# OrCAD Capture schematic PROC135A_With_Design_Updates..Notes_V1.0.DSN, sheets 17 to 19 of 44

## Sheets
17 17. M.2 CONNECTOR: size C; title: M.2 CONNECTOR I/F
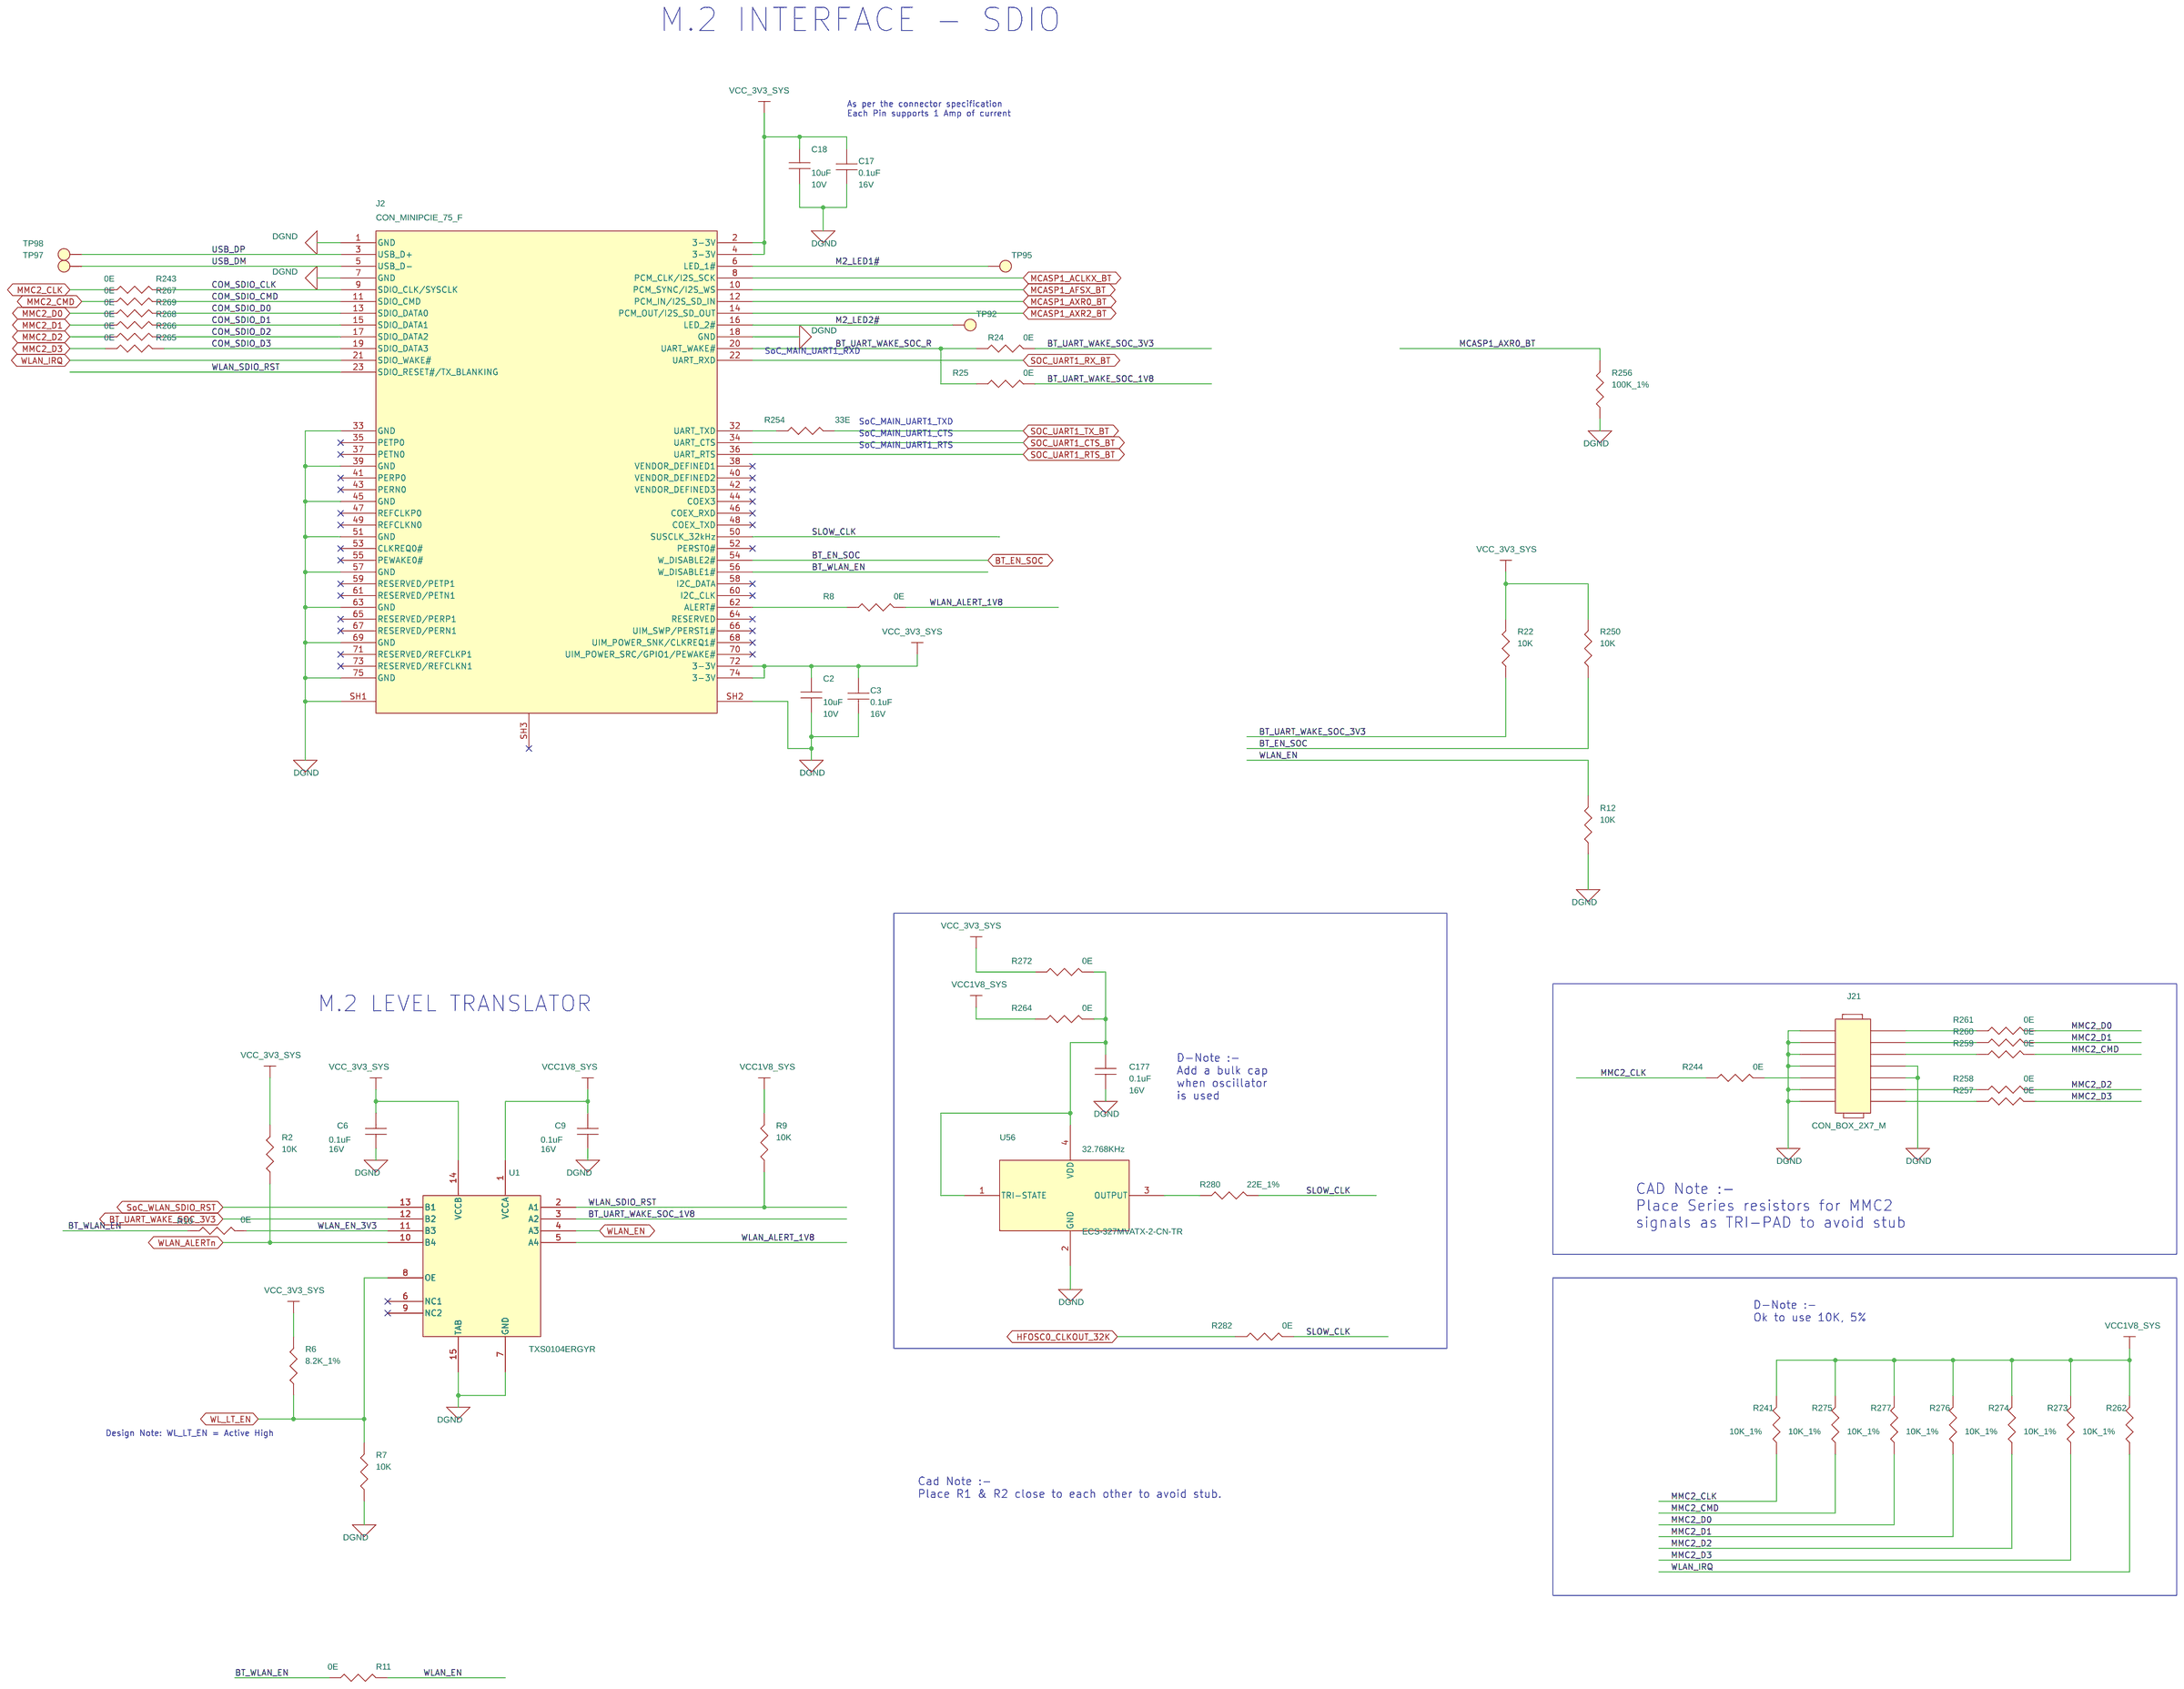
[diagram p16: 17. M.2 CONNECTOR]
18 18. eMMC FLASH: size C; title: eMMC FLASH INTERFACE
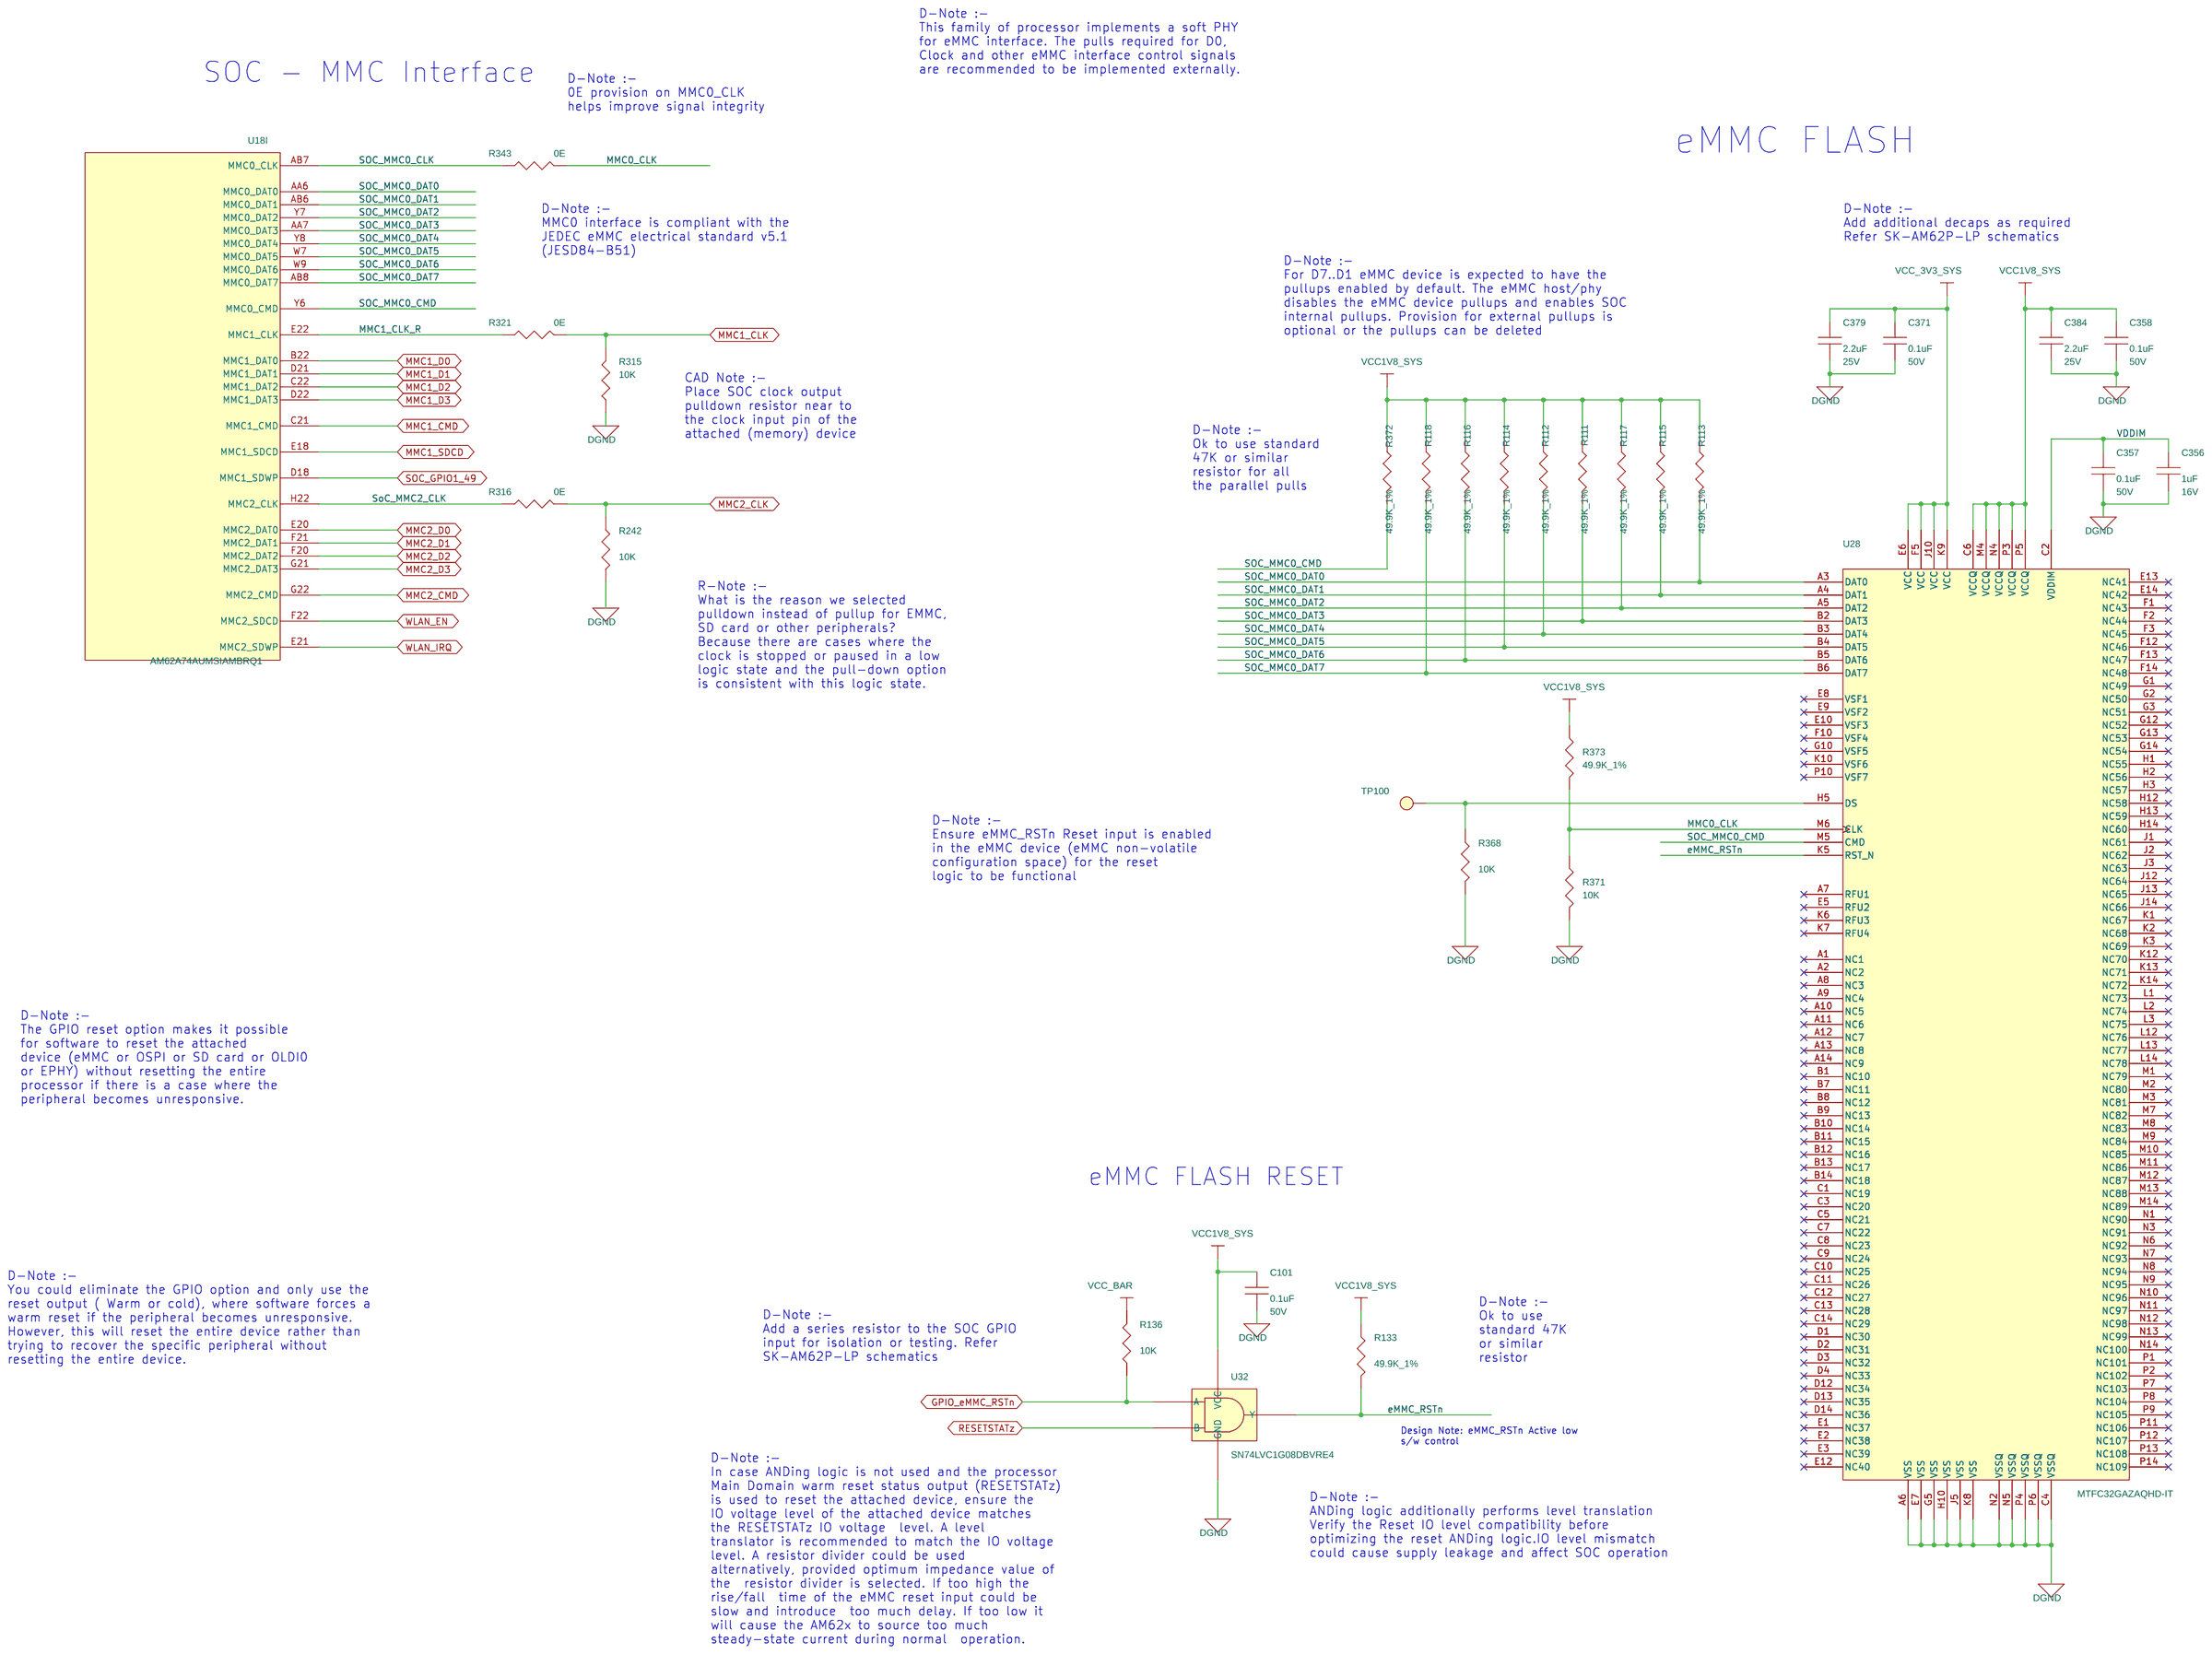
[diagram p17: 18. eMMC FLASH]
19 19. SD CARD INTERFACE: size C; title: SD CARD INTERFACE
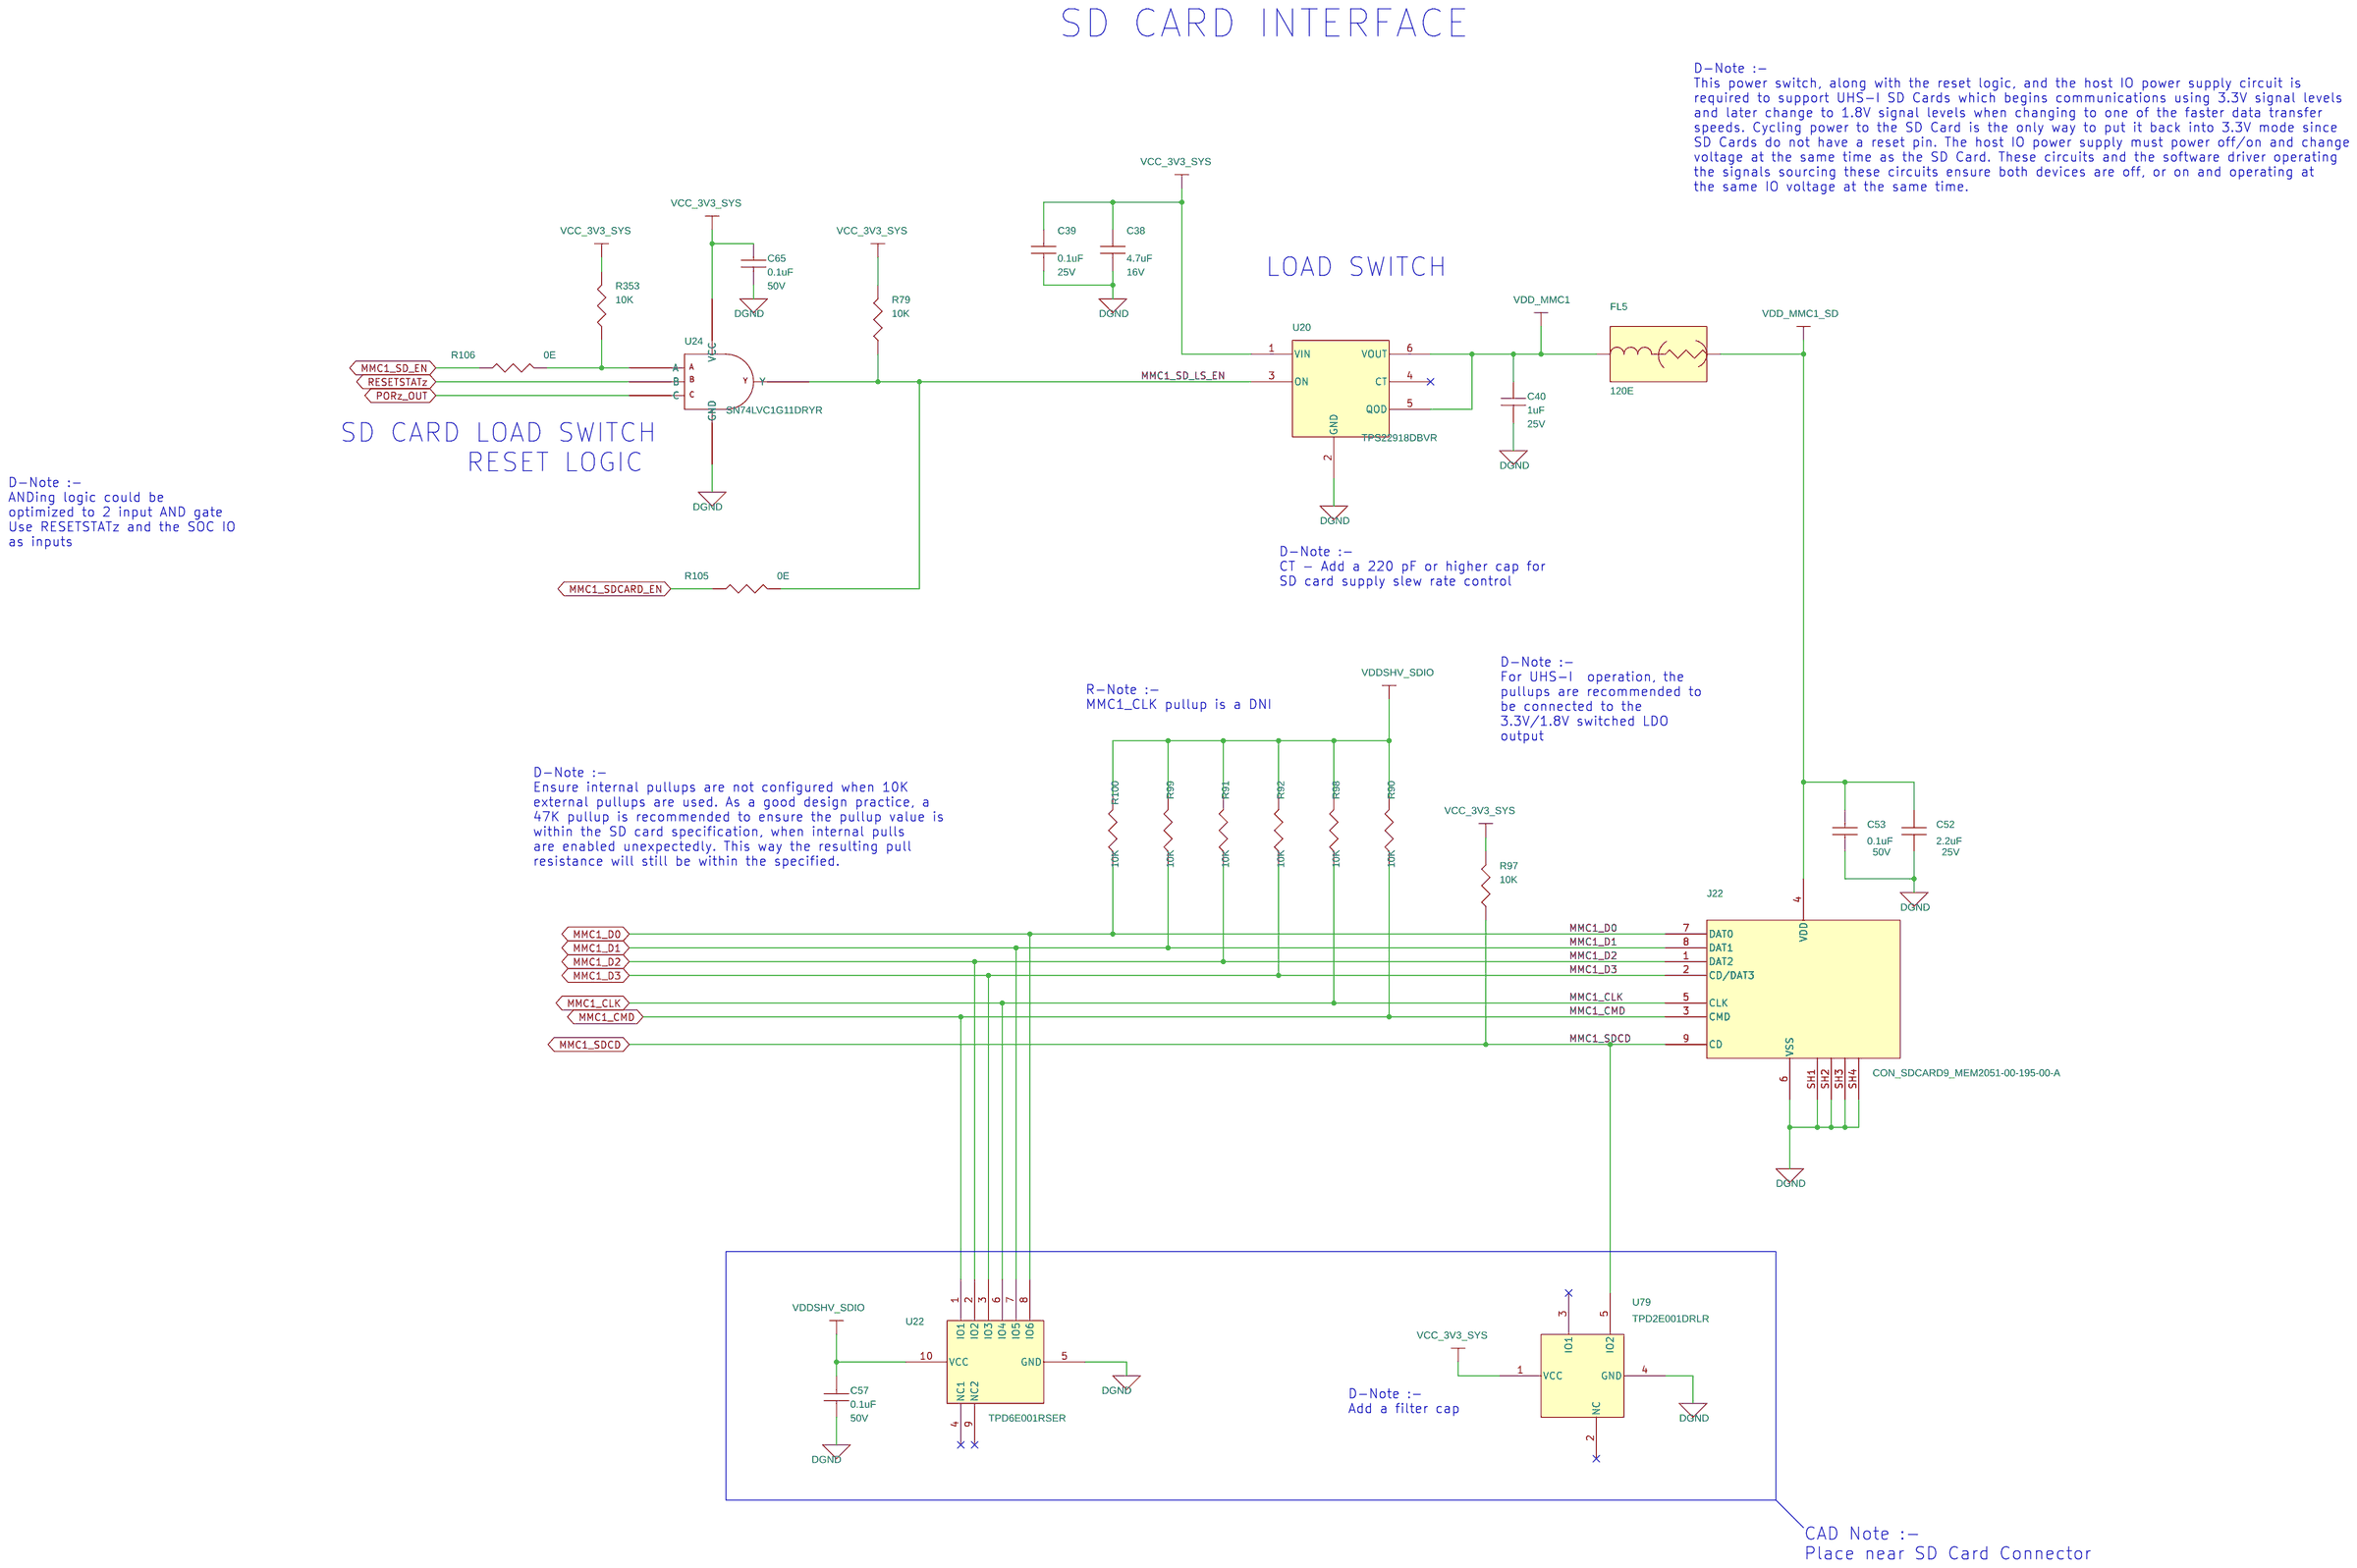
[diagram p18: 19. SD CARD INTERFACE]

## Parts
sheet 17. M.2 CONNECTOR
C2  10uF  [CAP0402_0-75]
C3  0.1uF  [CAP0201_0-5]
C6  0.1uF  [CAP0201_0-5]
C9  0.1uF  [CAP0201_0-5]
C17  0.1uF  [CAP0201_0-5]
C18  10uF  [CAP0402_0-75]
C177  0.1uF  [CAP0201_0-5]
J2  CON_MINIPCIE_75_F  [CON_MINIPCI75_2199119-4_S_R_S_3-2_2230]
J21  CON_BOX_2X7_M  [CON_BOX2X7_3020-14-0300-00_P_S_S_10-4]
R2  10K  [RES0201_0-5]
R6  8.2K_1%  [RES0201_0-5]
R7  10K  [RES0201_0-5]
R8  0E  [RES0201_0-5]
R9  10K  [RES0201_0-5]
R10  0E  [RES0201_0-5]
R11  0E  [RES0201_0-5]
R12  10K  [RES0201_0-5]
R22  10K  [RES0201_0-5]
R24  0E  [RES0201_0-5]
R25  0E  [RES0201_0-5]
R241  10K_1%  [RES0201_0-5]
R243  0E  [RES0201_0-5]
R244  0E  [RES0201_0-5]
R250  10K  [RES0201_0-5]
R254  33E  [RES0201_0-5]
R256  100K_1%  [RES0402_0-5]
R257  0E  [RES0201_0-5]
R258  0E  [RES0201_0-5]
R259  0E  [RES0201_0-5]
R260  0E  [RES0201_0-5]
R261  0E  [RES0201_0-5]
R262  10K_1%  [RES0201_0-5]
R264  0E  [RES0201_0-5]
R265  0E  [RES0201_0-5]
R266  0E  [RES0201_0-5]
R267  0E  [RES0201_0-5]
R268  0E  [RES0201_0-5]
R269  0E  [RES0201_0-5]
R272  0E  [RES0201_0-5]
R273  10K_1%  [RES0201_0-5]
R274  10K_1%  [RES0201_0-5]
R275  10K_1%  [RES0201_0-5]
R276  10K_1%  [RES0201_0-5]
R277  10K_1%  [RES0201_0-5]
R280  22E_1%  [RES0201_0-5]
R282  0E  [RES0201_0-5]
TP92  TP20_SMD  [TP20_SMD]
TP95  TP20_SMD  [TP20_SMD]
TP97  TP20_SMD  [TP20_SMD]
TP98  TP20_SMD  [TP20_SMD]
U1  TXS0104ERGYR  [QFN14_19-68_145X145]
U56  32.768KHz  [OSC4_ECS-327MVATX-2_100X80_SMD_1]
sheet 18. eMMC FLASH
C101  0.1uF  [CAP0402_0-75]
C356  1uF  [CAP0201_0-5]
C357  0.1uF  [CAP0402_0-75]
C358  0.1uF  [CAP0402_0-75]
C371  0.1uF  [CAP0402_0-75]
C379  2.2uF  [CAP0402_0-75]
C384  2.2uF  [CAP0402_0-75]
R111  49.9K_1%  [RES0201_0-5]
R112  49.9K_1%  [RES0201_0-5]
R113  49.9K_1%  [RES0201_0-5]
R114  49.9K_1%  [RES0201_0-5]
R115  49.9K_1%  [RES0201_0-5]
R116  49.9K_1%  [RES0201_0-5]
R117  49.9K_1%  [RES0201_0-5]
R118  49.9K_1%  [RES0201_0-5]
R133  49.9K_1%  [RES0201_0-5]
R136  10K  [RES0201_0-5]
R242  10K  [RES0201_0-5]
R315  10K  [RES0201_0-5]
R316  0E  [RES0201_0-5]
R321  0E  [RES0201_0-5]
R343  0E  [RES0201_0-5]
R368  10K  [RES0201_0-5]
R371  10K  [RES0201_0-5]
R372  49.9K_1%  [RES0201_0-5]
R373  49.9K_1%  [RES0201_0-5]
TP100  TP20_SMD  [TP20_SMD]
U28  MTFC32GAZAQHD-IT  [VFBGA153_19-68_460X520_0-9]
U32  SN74LVC1G08DBVRE4  [SOT23-5]
sheet 19. SD CARD INTERFACE
C38  4.7uF  [CAP0402_0-75]
C39  0.1uF  [CAP0201_0-5]
C40  1uF  [CAP0402_0-75]
C52  2.2uF  [CAP0402_0-75]
C53  0.1uF  [CAP0402_0-75]
C57  0.1uF  [CAP0402_0-75]
C65  0.1uF  [CAP0402_0-75]
FL5  120E  [EMIFIL_BLM15A_0402_0-6]
J22  CON_SDCARD9_MEM2051-00-195-00-A  [CON_SD9_MEM2051-00-195-00_S_R_S_2-1]
R79  10K  [RES0201_0-5]
R90  10K  [RES0201_0-5]
R91  10K  [RES0201_0-5]
R92  10K  [RES0201_0-5]
R97  10K  [RES0201_0-5]
R98  10K  [RES0201_0-5]
R99  10K  [RES0201_0-5]
R100  10K  [RES0201_0-5]
R105  0E  [RES0201_0-5]
R106  0E  [RES0201_0-5]
R353  10K  [RES0201_0-5]
U20  TPS22918DBVR  [SOT23-6]
U22  TPD6E001RSER  [UQFN10_19-68_80X60_0-6]
U24  SN74LVC1G11DRYR  [SON6_SN74LVC2G17_40X60_0-6]
U79  TPD2E001DRLR  [SOT553-5_0-6]
sheet 41. OSCILLATOR
U18  AM62A74AUMSIAMBRQ1  [FBGA484_31-49_710X710_2-7]  (sections A,B,C,D,E,F,G,H,I,J,K,L,M,N,O,P,Q)

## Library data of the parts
C2 C18 = CAP: CAP CERAMIC 10uF 10V 20% X5R 0402; Chkd/date: MANIRAJA/300520; Crtd /date: ALVY/260520; Custom_Duty: 15%; Customs_HS_Code: 85322990; Distributor_name: DIGIKEY; Distributor_part_number: 490-GRM155R61A106ME11DTR-ND; Footprint Path: Y:\MIS_DATABASE\Library\ALTIUM_TOOL\PCB_FOOTPRINTS\Altium_Footprint_Lib.PcbLib; Height: 0.55MM; Library Path: Y:\MIS_DATABASE\Library\ALTIUM_TOOL\SCHEMATICS_PARTS\MS_DISCRETE_Library.schlib; Mfr_name: MURATA; Mfr_part_number: GRM155R61A106ME11D; Mistral Part No: 120013110019-R; Package: 0402; Part_type: CAPACITORS\CERAMIC; Project: QCS610_NANOSOM; RoHS: RoHS; Temperature: -55°C+85°C; Tolerance: 20%; Voltage: 10V; Wattage: NA; Weight: 3.1mg; Datasheet: Y:\MIS_DATABASE\DATASHEETS\CAPACITORS\MURATA-GXX-SER_NOV17.PDF
C3 C6 C9 C17 C177 = CAP: CAP CERAMIC 0.1uF 16V 10% X5R 0201; Alt_Mfr_name: YAGEO AMERICA; Alt_Mfr_part_number: CC0402KRX5R8BB104; Chkd/date: MANIRAJA/230118; Crtd /date: MANIRAJA/230118; Custom_Duty: 15%; Customs_HS_Code: 85322990; Distributor_name: DIGIKEY; Distributor_part_number: 490-14305-1-ND; Footprint Path: Y:\MIS_DATABASE\Library\ALTIUM_TOOL\PCB_FOOTPRINTS\Altium_Footprint_Lib.PcbLib; Height: 0.33MM; Library Path: Y:\MIS_DATABASE\Library\ALTIUM_TOOL\SCHEMATICS_PARTS\MS_DISCRETE_Library.schlib; Mfr_name: MURATA; Mfr_part_number: GRM033R61C104KE14D; Mistral Part No: 120009030072-R; Package: 0201; Part_type: CAPACITORS\CERAMIC; Project: TI_MAXIE_CPB; RoHS: RoHS; Temperature: -55°C+85°C; Tolerance: 10%; Voltage: 16V; Wattage: NA; Weight: 0.33mg; Datasheet: Y:\MIS_DATABASE\DATASHEETS\CAPACITORS\GRM033R61C104KE14.PDF
J2 = CON_PCI_75_2199119-4_2230: CON MINIPCI 75POS 0.50MM PITCH FEMALE RT SMD; Chkd/date: ALVY/300521; Crtd /date: ALVY/300521; Custom_Duty: 24%; Customs_HS_Code: 85369090; Distributor_name: DIGIKEY; Distributor_part_number: A115900CT-ND; Footprint Path: Y:\MIS_DATABASE\Library\ALTIUM_TOOL\PCB_FOOTPRINTS\Altium_Footprint_Lib.PcbLib; Height: 3.20MM; Library Path: Y:\MIS_DATABASE\Library\ALTIUM_TOOL\SCHEMATICS_PARTS\MS_CONNECTOR_Library.schlib; Mfr_name: TE CONNECTIVITY; Mfr_part_number: 2199119-4_2230; Mistral Part No: 150021030016-R; Package: SMD; Part_type: CONNECTOR\PCI; Project: VOLTA_CHARGER V5; RoHS: RoHS; Temperature: -40°C+80°C; Tolerance: NA; Voltage: NA; Wattage: NA; Weight: 506mg; Datasheet: Y:\MIS_DATABASE\DATASHEETS\CONNECTORS\2199119.PDF
J21 = HEADER_7X2: CON BOX 2X7 2.54MM PITCH MALE ST SMD; Chkd/date: MANIRAJA/080921; Crtd /date: ALVY/080921; Custom_Duty: 24%; Customs_HS_Code: 85369090; Distributor_name: DIGIKEY; Distributor_part_number: 1175-1622-ND; Footprint Path: Y:\MIS_DATABASE\Library\ALTIUM_TOOL\PCB_FOOTPRINTS\Altium_Footprint_Lib.PcbLib; Height: 10.32MM; Library Path: Y:\MIS_DATABASE\Library\ALTIUM_TOOL\SCHEMATICS_PARTS\MS_CONNECTOR_Library.schlib; Mfr_name: CnC TECH; Mfr_part_number: 3020-14-0300-00; Mistral Part No: 150021090012-R; Package: SMD; Part_type: CONNECTOR\BOX HEADERS; Project: TI_AM335x SK_BRD; RoHS: RoHS; Temperature: -40°C+105°C; Tolerance: NA; Voltage: NA; Wattage: NA; Weight: NA; Datasheet: Y:\MIS_DATABASE\DATASHEETS\CONNECTORS\3020-XX-0300-00.PDF
R2 R7 R9 R12 R22 R79 R90-R92 R97-R100 R136 R242 R250 R315 R353 R368 R371 = RESISTOR: RES 10K 1/20W 5% 0201; Chkd/date: MANIRAJA/050517; Crtd /date: MANIRAJA/050517; Custom_Duty: 15%; Customs_HS_Code: 85332119; Distributor_name: DIGIKEY; Distributor_part_number: 311-10KNCT-ND; Footprint Path: Y:\MIS_DATABASE\Library\ALTIUM_TOOL\PCB_FOOTPRINTS\Altium_Footprint_Lib.PcbLib; Height: 0.26MM; Library Path: Y:\MIS_DATABASE\Library\ALTIUM_TOOL\SCHEMATICS_PARTS\MS_DISCRETE_Library.schlib; Mfr_name: YAGEO AMERICA; Mfr_part_number: RC0201JR-0710KL; Mistral Part No: 110010070051-R; Package: 0201; Part_type: RESISTORS\FIXED; Project: GOLDEN-I LITE; RoHS: RoHS; Temperature: -55°C+125°C; Tolerance: 5%; Voltage: NA; Wattage: 1/20W; Weight: 0.17mg; Datasheet: Y:\MIS_DATABASE\DATASHEETS\RESISTORS\RCXXXXL-SER_MAR18.PDF
R6 = RESISTOR: RES 8.2K 1/20W 1% 0201; Chkd/date: SUHAS/230910; Crtd /date: MUDDU/060710; Custom_Duty: 15%; Customs_HS_Code: 85332119; Distributor_name: DIGIKEY; Distributor_part_number: 541-8.20KAABCT-ND; Footprint Path: Y:\MIS_DATABASE\Library\ALTIUM_TOOL\PCB_FOOTPRINTS\Altium_Footprint_Lib.PcbLib; Height: 0.28MM; Library Path: Y:\MIS_DATABASE\Library\ALTIUM_TOOL\SCHEMATICS_PARTS\MS_DISCRETE_Library.schlib; Mfr_name: VISHAY; Mfr_part_number: CRCW02018K20FKED; Mistral Part No: 110010070001-R; Package: 0201; Part_type: RESISTORS\FIXED; Project: PB_BUGBASE; RoHS: RoHS; Temperature: -55°C+155°C; Tolerance: 1%; Voltage: NA; Wattage: 1/20W; Weight: 0.17mg; Datasheet: Y:\MIS_DATABASE\DATASHEETS\RESISTORS\CRCW0201.PDF
R8 R10 R11 R24 R25 R105 R106 R243 R244 R257-R261 R264-R269 R272 R282 = RESISTOR: RES 0E 1/20W 5% 0201; Chkd/date: NAVEED/301214; Crtd /date: MUDDU/120710; Custom_Duty: 15%; Customs_HS_Code: 85332119; Distributor_name: DIGIKEY; Distributor_part_number: 311-0.0NCT-ND; Footprint Path: Y:\MIS_DATABASE\Library\ALTIUM_TOOL\PCB_FOOTPRINTS\Altium_Footprint_Lib.PcbLib; Height: 0.26MM; Library Path: Y:\MIS_DATABASE\Library\ALTIUM_TOOL\SCHEMATICS_PARTS\MS_DISCRETE_Library.schlib; Mfr_name: YAGEO AMERICA; Mfr_part_number: RC0201JR-070RL; Mistral Part No: 110010070067-R; Package: 0201; Part_type: RESISTORS\FIXED; Project: PB_BUGBASE; RoHS: RoHS; Temperature: -55°C+125°C; Tolerance: 5%; Voltage: NA; Wattage: 1/20W; Weight: 0.17mg; Datasheet: Y:\MIS_DATABASE\DATASHEETS\RESISTORS\RCXXXXL-SER_MAR18.PDF
R241 R262 R273-R277 = RESISTOR: RES 10K 1/20W 1% 0201; Chkd/date: VASANTHA/270117; Crtd /date: MANIRAJA/270117; Custom_Duty: 15%; Customs_HS_Code: 85332119; Distributor_name: DIGIKEY; Distributor_part_number: 311-10.0KMCT-ND; Footprint Path: Y:\MIS_DATABASE\Library\ALTIUM_TOOL\PCB_FOOTPRINTS\Altium_Footprint_Lib.PcbLib; Height: 0.26MM; Library Path: Y:\MIS_DATABASE\Library\ALTIUM_TOOL\SCHEMATICS_PARTS\MS_DISCRETE_Library.schlib; Mfr_name: YAGEO AMERICA; Mfr_part_number: RC0201FR-0710KL; Mistral Part No: 110011040018-R; Package: 0201; Part_type: RESISTORS\FIXED; Project: GOLDEN-I LITE; RoHS: RoHS; Temperature: -55°C+125°C; Tolerance: 1%; Voltage: NA; Wattage: 1/20W; Weight: 0.17mg; Datasheet: Y:\MIS_DATABASE\DATASHEETS\RESISTORS\RCXXXXL-SER_MAR18.PDF
R254 = RESISTOR: RES 33E 1/20W 5% 0201; Chkd/date: MANIRAJA/050517; Crtd /date: MANIRAJA/050517; Custom_Duty: 15%; Customs_HS_Code: 85332119; Distributor_name: DIGIKEY; Distributor_part_number: 311-33NCT-ND; Footprint Path: Y:\MIS_DATABASE\Library\ALTIUM_TOOL\PCB_FOOTPRINTS\Altium_Footprint_Lib.PcbLib; Height: 0.26MM; Library Path: Y:\MIS_DATABASE\Library\ALTIUM_TOOL\SCHEMATICS_PARTS\MS_DISCRETE_Library.schlib; Mfr_name: YAGEO AMERICA; Mfr_part_number: RC0201JR-0733RL; Mistral Part No: 110010070052-R; Package: 0201; Part_type: RESISTORS\FIXED; Project: GOLDEN-I LITE; RoHS: RoHS; Temperature: -55°C+125°C; Tolerance: 5%; Voltage: NA; Wattage: 1/20W; Weight: 0.17mg; Datasheet: Y:\MIS_DATABASE\DATASHEETS\RESISTORS\RCXXXXL-SER_MAR18.PDF
R256 = RESISTOR: RES 100K 1/10W 1% 0402; Chkd/date: VASANTHA/201216; Crtd /date: MAZHAR/130306; Custom_Duty: 15%; Customs_HS_Code: 85332119; Distributor_name: DIGIKEY; Distributor_part_number: P100KLCT-ND; Footprint Path: Y:\MIS_DATABASE\Library\ALTIUM_TOOL\PCB_FOOTPRINTS\Altium_Footprint_Lib.PcbLib; Height: 0.40MM; Library Path: Y:\MIS_DATABASE\Library\ALTIUM_TOOL\SCHEMATICS_PARTS\MS_DISCRETE_Library.schlib; Mfr_name: PANASONIC-ECG; Mfr_part_number: ERJ-2RKF1003X; Mistral Part No: 110009030187-R; Package: 0402; Part_type: RESISTORS\FIXED; Project: J32; RoHS: RoHS; Temperature: -55°C+155°C; Tolerance: 1%; Voltage: NA; Wattage: 1/10W; Weight: 0.8mg; Datasheet: Y:\MIS_DATABASE\DATASHEETS\RESISTORS\PAN-ERJSER_NOV17.PDF
R280 = RESISTOR: RES 22E 1/20W 1% 0201; Chkd/date: MANIRAJA/080319; Crtd /date: ALVY/080319; Custom_Duty: 15%; Customs_HS_Code: 85332119; Distributor_name: DIGIKEY; Distributor_part_number: YAG2518CT-ND; Footprint Path: Y:\MIS_DATABASE\Library\ALTIUM_TOOL\PCB_FOOTPRINTS\Altium_Footprint_Lib.PcbLib; Height: 0.26MM; Library Path: Y:\MIS_DATABASE\Library\ALTIUM_TOOL\SCHEMATICS_PARTS\MS_DISCRETE_Library.schlib; Mfr_name: YAGEO AMERICA; Mfr_part_number: RC0201FR-0722RL; Mistral Part No: 110009030522-R; Package: 0201; Part_type: RESISTORS\FIXED; Project: AM654x_SOM; RoHS: RoHS; Temperature: -55°C+125°C; Tolerance: 1%; Voltage: NA; Wattage: 1/20W; Weight: 0.17mg; Datasheet: Y:\MIS_DATABASE\DATASHEETS\RESISTORS\RCXXXXL-SER_MAR18.PDF
TP92 TP95 TP97 TP98 TP100 = TESTPOINT: TESTPOINT CIR 20 SMD; Chkd/date: SHREESHAIL/171006; Crtd /date: MAZHAR/171006; Custom_Duty: NA; Customs_HS_Code: NA; Distributor_name: NA; Distributor_part_number: NA; Footprint Path: Y:\MIS_DATABASE\Library\ALTIUM_TOOL\PCB_FOOTPRINTS\Altium_Footprint_Lib.PcbLib; Height: NA; Library Path: Y:\MIS_DATABASE\Library\ALTIUM_TOOL\SCHEMATICS_PARTS\MS_DISCRETE_Library.schlib; MECHANICAL 3D STEP FILE: NA; Mfr_name: LOCAL; Mistral Part No: NA; Package: SMD; Project: BT MODULE_CSRBC04; RoHS: NA; Temperature: NA; Tolerance: NA; Voltage: NA; Wattage: NA; Weight: NA; Datasheet: NA
U1 = TXS0104ERGYR_QFN14: IC 4-BIT BIDIRECTIONAL VOLTAGE-LEVEL TRANSLATOR QFN14; Chkd/date: SHREESHAIL/170108; Crtd /date: SHREESHAIL/170108; Custom_Duty: 15%; Customs_HS_Code: 85423100; Distributor_name: DIGIKEY; Distributor_part_number: 296-20698-1-ND; Height: 1.00MM; Mfr_name: TEXAS INSTRUMENTS; Mistral Part No: 141009030362-R; Package: QFN14; Part_type: ICS\INTERFACE; Project: HS100RD; RoHS: Sb/ Br FREE; Datasheet: Y:\MIS_DATABASE\DATASHEETS\ICS\INTERFACE\TXS0104E.PDF
U56 = OSC4_ASFL3: OSC 32.768KHz CMOS SMD; Chkd/date: ALVY/030620; Crtd /date: MANIRAJA/030620; Custom_Duty: 24%; Customs_HS_Code: 85437099; Distributor_name: DIGIKEY; Distributor_part_number: XC3154CT-ND; Footprint Path: Y:\MIS_DATABASE\Library\ALTIUM_TOOL\PCB_FOOTPRINTS\Altium_Footprint_Lib.PcbLib; Height: 1.00MM; Library Path: Y:\MIS_DATABASE\Library\ALTIUM_TOOL\SCHEMATICS_PARTS\MS_DISCRETE_Library.schlib; Mfr_name: ECS INC; Mfr_part_number: ECS-327MVATX-2-CN-TR; Mistral Part No: 130020060007-R; Package: SMD; Part_type: OSCILLATORS; Project: JETSON_CARRIER_BRD; RoHS: RoHS; Temperature: -40°C+85°C; Tolerance: NA; Voltage: NA; Wattage: NA; Weight: NA; Datasheet: Y:\MIS_DATABASE\DATASHEETS\MISC\CRY_OSC\ECS-327MVATX.PDF
C53 C57 C65 C101 C357 C358 C371 = CAP: CAP CERAMIC 0.1uF 50V 10% X7R 0402; Alt_Mfr_name: YAGEO AMERICA; Alt_Mfr_part_number: CC0402KRX5R8BB104; Chkd/date: MANIRAJA/261020; Crtd /date: ALVY/211020; Custom_Duty: 15%; Customs_HS_Code: 85322990; Distributor_name: DIGIKEY; Distributor_part_number: 490-10700-1-ND; Footprint Path: Y:\MIS_DATABASE\Library\ALTIUM_TOOL\PCB_FOOTPRINTS\Altium_Footprint_Lib.PcbLib; Height: 0.55MM; Library Path: Y:\MIS_DATABASE\Library\ALTIUM_TOOL\SCHEMATICS_PARTS\MS_DISCRETE_Library.schlib; Mfr_name: MURATA; Mfr_part_number: GRM155R71H104KE14D; Mistral Part No: 120011100014-R; Package: 0402; Part_type: CAPACITORS\CERAMIC; Project: J7_CP; RoHS: RoHS; Temperature: -55°C+125°C; Tolerance: 10%; Voltage: 50V; Wattage: NA; Weight: 3.1mg; Datasheet: Y:\MIS_DATABASE\DATASHEETS\CAPACITORS\GRM155R71H104KE14.PDF
C356 = CAP: CAP CERAMIC 1uF 16V 20% X5R 0201; Chkd/date: MANIRAJA/300520; Crtd /date: ALVY/260520; Custom_Duty: 15%; Customs_HS_Code: 85322990; Distributor_name: DIGIKEY; Distributor_part_number: 490-18654-1-ND; Footprint Path: Y:\MIS_DATABASE\Library\ALTIUM_TOOL\PCB_FOOTPRINTS\Altium_Footprint_Lib.PcbLib; Height: 0.39MM; Library Path: Y:\MIS_DATABASE\Library\ALTIUM_TOOL\SCHEMATICS_PARTS\MS_DISCRETE_Library.schlib; Mfr_name: MURATA; Mfr_part_number: GRM033R61C105ME15D; Mistral Part No: 120018090038-R; Package: 0201; Part_type: CAPACITORS\CERAMIC; Project: QCS610_NANOSOM; RoHS: RoHS; Temperature: -55°C+85°C; Tolerance: 20%; Voltage: 16V; Wattage: NA; Weight: 0.33mg; Datasheet: Y:\MIS_DATABASE\DATASHEETS\CAPACITORS\GRM033R61C105ME15.PDF
C52 C379 C384 = CAP: CAP CERAMIC 2.2uF 25V 10% X5R 0402; Chkd/date: ALVY/010721; Crtd /date: MANIRAJA/010721; Custom_Duty: 15%; Customs_HS_Code: 85322990; Distributor_name: DIGIKEY; Distributor_part_number: 490-12703-1-ND; Footprint Path: Y:\MIS_DATABASE\Library\ALTIUM_TOOL\PCB_FOOTPRINTS\Altium_Footprint_Lib.PcbLib; Height: 0.70MM; Library Path: Y:\MIS_DATABASE\Library\ALTIUM_TOOL\SCHEMATICS_PARTS\MS_DISCRETE_Library.schlib; Mfr_name: MURATA; Mfr_part_number: GRM155R61E225KE11D; Mistral Part No: 120015120001-R; Package: 0402; Part_type: CAPACITORS\CERAMIC; Project: TI_AM263X_CC; RoHS: RoHS; Temperature: -55°C+85°C; Tolerance: 10%; Voltage: 25V; Wattage: NA; Weight: 1.5mg; Datasheet: Y:\MIS_DATABASE\DATASHEETS\CAPACITORS\GRM155R61E225KE11.PDF
R111 R112 R114-R118 R373 = RESISTOR: RES 49.9K 1/20W 1% 0201; Chkd/date: MAZHAR/140108; Crtd /date: USMAN/140108; Cust_part_number: 4700-80185E; Custom_Duty: 15%; Customs_HS_Code: 85332119; Distributor_name: DIGIKEY; Distributor_part_number: P49.9KABCT-ND; Footprint Path: Y:\MIS_DATABASE\Library\ALTIUM_TOOL\PCB_FOOTPRINTS\Altium_Footprint_Lib.PcbLib; Height: 0.26MM; Library Path: Y:\MIS_DATABASE\Library\ALTIUM_TOOL\SCHEMATICS_PARTS\MS_DISCRETE_Library.schlib; Mfr_name: PANASONIC-ECG; Mfr_part_number: ERJ-1GEF4992C; Mistral Part No: 110009030900-R; Package: 0201; Part_type: RESISTORS\FIXED; Project: SD_WATERLOO; RoHS: RoHS; Temperature: -55°C+125°C; Tolerance: 1%; Voltage: NA; Wattage: 1/20W; Weight: 0.15mg; Datasheet: Y:\MIS_DATABASE\DATASHEETS\RESISTORS\PAN-ERJSER_NOV17.PDF
R113 R133 R372 = RESISTOR: RES 49.9K 1/20W 1% 0201; Chkd/date: PRAVEEN/260822; Crtd /date: PRAVEEN/260822; Custom_Duty: 15%; Customs_HS_Code: 85332119; Distributor_name: DIGIKEY; Distributor_part_number: RMCF0201FT49K9CT-ND; Footprint Path: Y:\MIS_DATABASE\Library\ALTIUM_TOOL\PCB_FOOTPRINTS\Altium_Footprint_Lib.PcbLib; Height: 0.28MM; Library Path: Y:\MIS_DATABASE\Library\ALTIUM_TOOL\SCHEMATICS_PARTS\MS_DISCRETE_Library.schlib; Mfr_name: STACKPOLE ELECTRONICS; Mfr_part_number: RMCF0201FT49K9; Mistral Part No: 110022080045-R; Package: 0201; Part_type: RESISTORS\FIXED; Project: MS_TI_TMDS64SKEVM; RoHS: RoHS; Temperature: -55°C+155°C; Tolerance: 1%; Voltage: NA; Wattage: 1/20W; Weight: 0.16mg; Datasheet: Y:\MIS_DATABASE\DATASHEETS\RESISTORS\RMCF-SER_JUL18.PDF
R316 R321 = RESISTOR: RES 0E 1/20W 5% 0201; Chkd/date: NAVEED/301214; Crtd /date: MUDDU/120710; Custom_Duty: 15%; Customs_HS_Code: 85332119; Distributor_name: DIGIKEY; Distributor_part_number: 311-0.0NCT-ND; Footprint Path: Y:\MIS_DATABASE\Library\ALTIUM_TOOL\PCB_FOOTPRINTS\Altium_Footprint_Lib.PcbLib; Height: 0.26MM; Library Path: Y:\MIS_DATABASE\Library\ALTIUM_TOOL\SCHEMATICS_PARTS\MS_DISCRETE_Library.schlib; Mfr_name: YAGEO AMERICA; Mfr_part_number: RC0201JR-070RL; Mistral Part No: 110010070067-R; Package: 0201; Part_type: RESISTORS\FIXED; Project: PB_BUGBASE; RoHS: RoHS; SIGNAL_MODEL: RESISTOR_RES0201_0-5_0E_0E; Temperature: -55°C+125°C; Tolerance: 5%; Voltage: NA; Wattage: 1/20W; Weight: 0.17mg; Datasheet: Y:\MIS_DATABASE\DATASHEETS\RESISTORS\RCXXXXL-SER_MAR18.PDF
R343 = RESISTOR: RES 0E 1/20W 5% 0201; Chkd/date: NAVEED/301214; Crtd /date: MUDDU/120710; Custom_Duty: 15%; Customs_HS_Code: 85332119; Distributor_name: DIGIKEY; Distributor_part_number: 311-0.0NCT-ND; Footprint Path: Y:\MIS_DATABASE\Library\ALTIUM_TOOL\PCB_FOOTPRINTS\Altium_Footprint_Lib.PcbLib; Height: 0.26MM; Library Path: Y:\MIS_DATABASE\Library\ALTIUM_TOOL\SCHEMATICS_PARTS\MS_DISCRETE_Library.schlib; Mfr_name: YAGEO AMERICA; Mfr_part_number: RC0201JR-070RL; Mistral Part No: 110010070067-R; Package: 0201; Part_type: RESISTORS\FIXED; Project: PB_BUGBASE; RoHS: RoHS; SIGNAL_MODEL: RESISTOR_RES0201_0-5_22E_1%_22E_1%; Temperature: -55°C+125°C; Tolerance: 5%; Voltage: NA; Wattage: 1/20W; Weight: 0.17mg; Datasheet: Y:\MIS_DATABASE\DATASHEETS\RESISTORS\RCXXXXL-SER_MAR18.PDF
U28 = MTFC16GAPALBH_TFBGA153: IC 32GB e-MMC MEMORY VFBGA153; Chkd/date: PRAVEEN/010922; Crtd /date: PRAVEEN/010922; Custom_Duty: 15%; Customs_HS_Code: 85423100; Distributor_name: DIGIKEY; Distributor_part_number: 557-MTFC32GAZAQHD-IT-ND; Footprint Path: Y:\MIS_DATABASE\Library\ALTIUM_TOOL\PCB_FOOTPRINTS\Altium_Footprint_Lib.PcbLib; Height: 0.90MM; Library Path: Y:\MIS_DATABASE\Library\ALTIUM_TOOL\SCHEMATICS_PARTS\MS_MISCMEMORY_Library.schlib; Mfr_name: MICRON; Mistral Part No: 141122090001-R; Package: VFBGA153; Part_type: ICS\DIGITAL\MEMORY; Project: J7AHP_SK_BRD; RoHS: RoHS; Temperature: -40°C+95°C; Tolerance: NA; Voltage: NA; Wattage: NA; Weight: NA; Datasheet: Y:\MIS_DATABASE\DATASHEETS\ICS\MEMORY\MTFC64GAZAQHD-IT.PDF
U32 = SN74LVC1G08DBVRE4_SOT23-5: IC SINGLE 2-INPUT POSITIVE AND GATE SOT23-5; Chkd/date: SUHAS/221010; Crtd /date: USMAN/151008; Custom_Duty: 15%; Customs_HS_Code: 85423100; Distributor_name: DIGIKEY; Distributor_part_number: SN74LVC1G08DBVRE4-ND; Height: 1.45MM; Mfr_name: TEXAS INSTRUMENTS; Mistral Part No: 141009060026-R; Part_type: ICS\DIGITAL\GATES; Project: KHAN_MAIN; RoHS: Sb/ Br FREE; Temperature: -40°C+85°C; Datasheet: Y:\MIS_DATABASE\DATASHEETS\ICS\DIGITAL\GATES\SN74LVC1G08.PDF
C38 = CAP: CAP CERAMIC 4.7uF 16V 20% X5R 0402; Alt_Mfr_name: YAGEO AMERICA; Alt_Mfr_part_number: CC0402KRX5R8BB104; Chkd/date: MANIRAJA/061218; Crtd /date: ALVY/061218; Custom_Duty: 15%; Customs_HS_Code: 85322990; Distributor_name: DIGIKEY; Distributor_part_number: 311-3482-1-ND; Footprint Path: Y:\MIS_DATABASE\Library\ALTIUM_TOOL\PCB_FOOTPRINTS\Altium_Footprint_Lib.PcbLib; Height: 0.65MM; Library Path: Y:\MIS_DATABASE\Library\ALTIUM_TOOL\SCHEMATICS_PARTS\MS_DISCRETE_Library.schlib; Mfr_name: YAGEO AMERICA; Mfr_part_number: CC0402MRX5R7BB475; Mistral Part No: 120017100010-R; Package: 0402; Part_type: CAPACITORS\CERAMIC; Project: RFSU_POC-CARD; RoHS: RoHS; Temperature: -55°C+85°C; Tolerance: 20%; Voltage: 16V; Wattage: NA; Weight: NA; Datasheet: Y:\MIS_DATABASE\DATASHEETS\CAPACITORS\YACC-X5R.PDF
C39 = CAP: CAP CERAMIC 0.1uF 25V 10% X5R 0201; Chkd/date: PRAVEEN/131222; Crtd /date: TAMILARASU/131222; Custom_Duty: 15%; Customs_HS_Code: 85322990; Distributor_name: DIGIKEY; Distributor_part_number: 490-12686-1-ND; Footprint Path: Y:\MIS_DATABASE\Library\ALTIUM_TOOL\PCB_FOOTPRINTS\Altium_Footprint_Lib.PcbLib; Height: 0.33MM; Library Path: Y:\MIS_DATABASE\Library\ALTIUM_TOOL\SCHEMATICS_PARTS\MS_DISCRETE_Library.schlib; Mfr_name: MURATA; Mfr_part_number: GRM033R61E104KE14D; Mistral Part No: 120022120017-R; Package: 0201; Part_type: CAPACITORS\CERAMIC; Project: CLOUD RADAR; RoHS: RoHS; Temperature: -55°C+85°C; Tolerance: 10%; Voltage: 25V; Wattage: NA; Weight: 0.33mg; Datasheet: Y:\MIS_DATABASE\DATASHEETS\CAPACITORS\GRM033R61E104KE14D.PDF
C40 = CAP: CAP CERAMIC 1uF 25V 10% X5R AUTO 0402; Chkd/date: MANIRAJA/290318; Crtd /date: ALVY/280318; Custom_Duty: 15%; Customs_HS_Code: 85322990; Distributor_name: DIGIKEY; Distributor_part_number: 490-12263-1-ND; Footprint Path: Y:\MIS_DATABASE\Library\ALTIUM_TOOL\PCB_FOOTPRINTS\Altium_Footprint_Lib.PcbLib; Height: 0.55MM; Library Path: Y:\MIS_DATABASE\Library\ALTIUM_TOOL\SCHEMATICS_PARTS\MS_DISCRETE_Library.schlib; Mfr_name: MURATA; Mfr_part_number: GRT155R61E105KE01D; Mistral Part No: 120019040035-R; Package: 0402; Part_type: CAPACITORS\CERAMIC; Project: NPOL_SAR_ADC; RoHS: RoHS; Temperature: -55°C+85°C; Tolerance: 10%; Voltage: 25V; Wattage: NA; Weight: 0.65mg; Datasheet: Y:\MIS_DATABASE\DATASHEETS\CAPACITORS\GRT155R61E105KE01D.PDF
FL5 = EMIFILTER_IND: IND FERRITE BEAD CHIP 120E 2A 0402; Chkd/date: NAVEED/241114; Crtd /date: USMAN/170613; Custom_Duty: 24%; Customs_HS_Code: 85369090; Distributor_name: DIGIKEY; Distributor_part_number: 490-9656-1-ND; Footprint Path: Y:\MIS_DATABASE\Library\ALTIUM_TOOL\PCB_FOOTPRINTS\Altium_Footprint_Lib.PcbLib; Height: 0.55MM; Library Path: Y:\MIS_DATABASE\Library\ALTIUM_TOOL\SCHEMATICS_PARTS\MS_FILTER_Library.schlib; Mfr_name: MURATA; Mfr_part_number: BLM15PX121SN1D; Mistral Part No: 130013060022-R; Package: 0402; Part_type: INDUCTOR; Project: GEN_3-8; RoHS: RoHS; Temperature: -55°C+125°C; Tolerance: 25%; Voltage: NA; Wattage: NA; Weight: 1mg; Datasheet: Y:\MIS_DATABASE\DATASHEETS\DISCRETES\INDUCTORS\BLM15-SN1-SER.PDF
J22 = CON_SDCARD9_MEM2075-00-140: CON MICROSD CARD 9POS FEMALE RT SMD; Chkd/date: MANIRAJA/270921; Crtd /date: ALVY/240921; Custom_Duty: 24%; Customs_HS_Code: 85369090; Distributor_name: DIGIKEY; Distributor_part_number: 2073-MEM2051-00-195-00-ACT-ND; Footprint Path: Y:\MIS_DATABASE\Library\ALTIUM_TOOL\PCB_FOOTPRINTS\Altium_Footprint_Lib.PcbLib; Height: 2.05MM; Library Path: Y:\MIS_DATABASE\Library\ALTIUM_TOOL\SCHEMATICS_PARTS\MS_CONNECTOR_Library.schlib; Mfr_name: GCT; Mfr_part_number: MEM2051-00-195-00-A; Mistral Part No: 150021090028-R; Package: SMD; Part_type: CONNECTOR\MEMORY CARD; Project: TI_AM62x SKEVM_BRD; RoHS: RoHS; Temperature: -40°C+85°C; Tolerance: NA; Voltage: NA; Wattage: NA; Weight: 1000mg; Datasheet: Y:\MIS_DATABASE\DATASHEETS\CONNECTORS\MEM2051-00-195-00-A.PDF
U20 = TPS22918DBVR_SOT23-6: IC ON RESISTANCE LOAD SWITCH SOT23-6; Automotive Alternate_mfr_name: TEXAS INSTRUMENTS; Automotive Alternate_mfr_part_number: TPS22918TDBVRQ1; Chkd/date: VASANTHA/130516; Crtd /date: VASANTHA/130516; Custom_Duty: 15%; Customs_HS_Code: 85423100; Distributor_name: DIGIKEY; Distributor_part_number: TPS22918DBVR-ND; Height: 1.45MM; Mfr_name: TEXAS INSTRUMENTS; Mistral Part No: 142016050007-R; Part_type: ICS\POWER; Project: TMDXCSK8127; RoHS: RoHS; Temperature: -40°C to 105°C; Tolerance: NA; Voltage: NA; Wattage: NA; Weight: NA; Datasheet: Y:\MIS_DATABASE\DATASHEETS\ICS\POWER\TPS22918DBV.PDF
U22 = TPD6E001RSE_UQFN10: IC 6CH ESD-PROTECTION ARRAY UQFN10; Chkd/date: USMAN/070612; Crtd /date: BAVISH/160811; Custom_Duty: 15%; Customs_HS_Code: 85423100; Distributor_name: DIGIKEY; Distributor_part_number: 296-21888-1-ND; Footprint Path: Y:\MIS_DATABASE\Library\ALTIUM_TOOL\PCB_FOOTPRINTS\Altium_Footprint_Lib.PcbLib; Height: 0.60MM; IBISSP_MODLES: Y:\MIS_DATABASE\IBIS\ICs\INTERFACE\TPD6E001RSE.IBS; Library Path: Y:\MIS_DATABASE\Library\ALTIUM_TOOL\SCHEMATICS_PARTS\MS_MISCINTERFACE_Library.schlib; Mfr_name: TEXAS INSTRUMENTS; Mistral Part No: 141011080020-R; Package: UQFN10; Part_type: ICS\INTERFACE; Project: DM385EVM_BASE-BOARD; RoHS: RoHS; Temperature: -40°C+85°C; Tolerance: NA; Voltage: NA; Wattage: NA; Weight: 7mg; Datasheet: Y:\MIS_DATABASE\DATASHEETS\ICS\INTERFACE\TPD6E001.PDF
U24 = SN74LVC1G11DCKR_SC70-6: IC SINGLE 3-INPUT POSITIVE-AND GATE SON6; Chkd/date: MANIRAJA/270121; Crtd /date: ALVY/270121; Custom_Duty: 15%; Customs_HS_Code: 85423100; Distributor_name: DIGIKEY; Distributor_part_number: 296-30120-1-ND; Footprint Path: Y:\MIS_DATABASE\Library\ALTIUM_TOOL\PCB_FOOTPRINTS\Altium_Footprint_Lib.PcbLib; Height: 0.60MM; Library Path: Y:\MIS_DATABASE\Library\ALTIUM_TOOL\SCHEMATICS_PARTS\MS_GATE_Library.schlib; Mfr_name: TEXAS INSTRUMENTS; Mistral Part No: 141021010013-R; Package: SON6; Part_type: ICS\DIGITAL\GATES; Project: AM64X_SKEVM; RoHS: RoHS; Temperature: -40°C+125°C; Tolerance: NA; Voltage: NA; Wattage: NA; Weight: 33mg; Datasheet: Y:\MIS_DATABASE\DATASHEETS\ICS\DIGITAL\GATES\SN74LVC1G_NOV16.PDF
U79 = TPD2E001DRLR_SOT-5: IC ESD-PROTECTION DIODE ARRAYS SOT-5; Chkd/date: NAVEED/150714; Crtd /date: MUDDU/250510; Custom_Duty: 15%; Customs_HS_Code: 85423100; Distributor_name: DIGIKEY; Distributor_part_number: 296-21883-1-ND; Footprint Path: Y:\MIS_DATABASE\Library\ALTIUM_TOOL\PCB_FOOTPRINTS\Altium_Footprint_Lib.PcbLib; Height: 0.60MM; Library Path: Y:\MIS_DATABASE\Library\ALTIUM_TOOL\SCHEMATICS_PARTS\MS_FILTER_Library.schlib; Mfr_name: TEXAS INSTRUMENTS; Mistral Part No: 140110060007-R; Package: SOT-5; Part_type: ICS\ANALOG\ACTIVE FILTER; Project: CENTAURUS; RoHS: RoHS; Temperature: -40°C+85°C; Tolerance: NA; Voltage: NA; Wattage: NA; Weight: 2.8mg; Datasheet: Y:\MIS_DATABASE\DATASHEETS\ICS\MISC\TPD2E001DRLR.PDF
U18 = AM62A-EVM_SOC_FCBGA484: IC AM62A SK EVM SoC MICROPROCESSOR FCBGA484; Chkd/date: PRADEEP/020823; Crtd /date: PRADEEP/020823; Custom_Duty: 15%; Customs_HS_Code: 85423100; Distributor_name: NA; Distributor_part_number: NA; Footprint Path: Y:\MIS_DATABASE\Library\ALTIUM_TOOL\PCB_FOOTPRINTS\Altium_Footprint_Lib.PcbLib; Height: 2.65MM; Library Ref: AM62A-EVM_SoC_FCBGA484; Mfr_name: TEXAS INSTRUMENTS; Mistral Part No: 141230080001-R; Package: FCBGA484; Part_type: ICS\DIGITAL\MICROPROCESSOR; Project: TI_AM62A_SK_EVM; RoHS: NA; Temperature: NA; Tolerance: NA; Voltage: NA; Wattage: NA; Weight: NA; Datasheet: Y:\MIS_DATABASE\DATASHEETS\ICS\DIGITAL\MICROCONTROLLER\AM62A_SK_EVM.PDF

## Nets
DGND: C2.2 C3.1 C6.1 C9.1 C17.1 C18.2 C38.2 C39.2 C40.2 C52.1 C53.1 C57.1 C65.2 C101.2 C177.2 C356.2 C357.2 C358.2 C371.2 C379.2 C384.2 J2.1(GND) J2.7(GND) J2.18(GND) J2.33(GND) J2.39(GND) J2.45(GND) J2.51(GND) J2.57(GND) J2.63(GND) J2.69(GND) J2.75(GND) J2.SH1 J2.SH2 J21.1 J21.3 J21.5 J21.7 J21.8 J21.10 J21.11 J21.13 J22.6(VSS) J22.SH1 J22.SH2 J22.SH3 J22.SH4 R7.1 R12.1 R242.2 R256.1 R315.2 R368.2 R371.2 U1.7(GND) U1.15(TAB) U20.2(GND) U22.5(GND) U24.2(GND) U28.A6(VSS) U28.C4(VSSQ) U28.E7(VSS) U28.G5(VSS) U28.H10(VSS) U28.J5(VSS) U28.K8(VSS) U28.N2(VSSQ) U28.N5(VSSQ) U28.P4(VSSQ) U28.P6(VSSQ) U32.3(GND) U56.2(GND) U79.4(GND) ; also on sheet 9 10 11 12 13 14 15 16 20 21 22 23 24 25 26 27 28 29 30 31 32 33 34 35 36 37 38 39 40 41 42 43
VCC1V8_SYS: C9.2 C101.1 C358.1 C384.1 R9.2 R111.1 R112.1 R113.1 R114.1 R115.1 R116.1 R117.1 R118.1 R133.1 R241.2 R262.2 R264.1 R273.2 R274.2 R275.2 R276.2 R277.2 R372.1 R373.1 U1.1(VCCA) U28.C6(VCCQ) U28.M4(VCCQ) U28.N4(VCCQ) U28.P3(VCCQ) U28.P5(VCCQ) U32.5(VCC) ; also on sheet 12 13 20 33 36 38 39 41
VCC_3V3_SYS: C2.1 C3.2 C6.2 C17.2 C18.1 C38.1 C39.1 C65.1 C371.1 C379.1 J2.2(3-3V) J2.4(3-3V) J2.72(3-3V) J2.74(3-3V) R2.2 R6.2 R22.2 R79.2 R97.2 R136.2 R250.2 R272.1 R353.2 U1.14(VCCB) U20.1(VIN) U24.5(VCC) U28.E6(VCC) U28.F5(VCC) U28.J10(VCC) U28.K9(VCC) U79.1(VCC) ; also on sheet 9 10 12 13 21 22 23 25 26 28 29 30 32 33 34 35 36 37 38 39 40 41 42
VDD_MMC1: C40.1 FL5.1 U20.5(QOD) U20.6(VOUT)
VDD_MMC1_SD: C52.2 C53.2 FL5.2 J22.4(VDD)
VDDIM: C356.1 C357.1 U28.C2(VDDIM)
VDDSHV_SDIO: C57.2 R90.2 R91.2 R92.2 R98.2 R99.2 R100.2 U22.10(VCC) ; also on sheet 12 14
BT_EN_SOC: J2.54(W_DISABLE2#) R250.1 ; also on sheet 39
BT_UART_WAKE_SOC_1V8: R25.2 U1.3(A2)
BT_UART_WAKE_SOC_3V3: R22.1 R24.2 U1.12(B2) ; also on sheet 39
BT_UART_WAKE_SOC_R: J2.20(UART_WAKE#) R24.1 R25.1
BT_WLAN_EN: J2.56(W_DISABLE1#) R10.1 R11.2
COM_SDIO_CLK: J2.9(SDIO_CLK/SYSCLK) R243.1
COM_SDIO_CMD: J2.11(SDIO_CMD) R267.1
COM_SDIO_D0: J2.13(SDIO_DATA0) R269.1
COM_SDIO_D1: J2.15(SDIO_DATA1) R268.1
COM_SDIO_D2: J2.17(SDIO_DATA2) R266.1
COM_SDIO_D3: J2.19(SDIO_DATA3) R265.1
eMMC_RSTn: R133.2 U28.K5(RST_N) U32.4(Y)
GPIO_eMMC_RSTn: R136.1 U32.1(A) ; also on sheet 39
HFOSC0_CLKOUT_32K: R282.1 ; also on sheet 31
M2_LED1#: J2.6(LED_1#) TP95.1(TP)
M2_LED2#: J2.16(LED_2#) TP92.1(TP)
MCASP1_ACLKX_BT: J2.8(PCM_CLK/I2S_SCK) ; also on sheet 39
MCASP1_AFSX_BT: J2.10(PCM_SYNC/I2S_WS) ; also on sheet 39
MCASP1_AXR0_BT: J2.12(PCM_IN/I2S_SD_IN) R256.2 ; also on sheet 39
MCASP1_AXR2_BT: J2.14(PCM_OUT/I2S_SD_OUT) ; also on sheet 39
MMC0_CLK: R343.1 R371.1 R373.2 U28.M6(CLK)
MMC1_CLK: J22.5(CLK) R98.1 R315.1 R321.1 U22.6(IO4)
MMC1_CLK_R: R321.2 U18.E22(MMC1_CLK)
MMC1_CMD: J22.3(CMD) R90.1 U18.C21(MMC1_CMD) U22.1(IO1)
MMC1_D0: J22.7(DAT0) R100.1 U18.B22(MMC1_DAT0) U22.8(IO6)
MMC1_D1: J22.8(DAT1) R99.1 U18.D21(MMC1_DAT1) U22.7(IO5)
MMC1_D2: J22.1(DAT2) R91.1 U18.C22(MMC1_DAT2) U22.2(IO2)
MMC1_D3: J22.2(CD/DAT3) R92.1 U18.D22(MMC1_DAT3) U22.3(IO3)
MMC1_SD_EN: R106.1 ; also on sheet 39
MMC1_SD_LS_EN: R79.1 R105.2 U20.3(ON) U24.4(Y)
MMC1_SDCARD_EN: R105.1 ; also on sheet 12
MMC1_SDCD: J22.9(CD) R97.1 U18.E18(MMC1_SDCD) U79.5(IO2)
MMC2_CLK: R241.1 R242.1 R243.2 R244.1 R316.2
MMC2_CMD: R259.2 R267.2 R275.1 U18.G22(MMC2_CMD)
MMC2_D0: R261.2 R269.2 R277.1 U18.E20(MMC2_DAT0)
MMC2_D1: R260.2 R268.2 R276.1 U18.F21(MMC2_DAT1)
MMC2_D2: R258.2 R266.2 R274.1 U18.F20(MMC2_DAT2)
MMC2_D3: R257.2 R265.2 R273.1 U18.G21(MMC2_DAT3)
PORz_OUT: U24.6(C) ; also on sheet 22 23 26 41
RESETSTATz: U24.3(B) U32.2(B) ; also on sheet 20 22 23 26 37 38 39 40 41
SLOW_CLK: J2.50(SUSCLK_32kHz) R280.2 R282.2
SOC_GPIO1_49: U18.D18(MMC1_SDWP) ; also on sheet 35
SOC_MMC0_CLK: R343.2 U18.AB7(MMC0_CLK)
SOC_MMC0_CMD: R372.2 U18.Y6(MMC0_CMD) U28.M5(CMD)
SOC_MMC0_DAT0: R113.2 U18.AA6(MMC0_DAT0) U28.A3(DAT0)
SOC_MMC0_DAT1: R115.2 U18.AB6(MMC0_DAT1) U28.A4(DAT1)
SOC_MMC0_DAT2: R117.2 U18.Y7(MMC0_DAT2) U28.A5(DAT2)
SOC_MMC0_DAT3: R111.2 U18.AA7(MMC0_DAT3) U28.B2(DAT3)
SOC_MMC0_DAT4: R112.2 U18.Y8(MMC0_DAT4) U28.B3(DAT4)
SOC_MMC0_DAT5: R114.2 U18.W7(MMC0_DAT5) U28.B4(DAT5)
SOC_MMC0_DAT6: R116.2 U18.W9(MMC0_DAT6) U28.B5(DAT6)
SOC_MMC0_DAT7: R118.2 U18.AB8(MMC0_DAT7) U28.B6(DAT7)
SoC_MMC2_CLK: R316.1 U18.H22(MMC2_CLK)
SOC_UART1_CTS_BT: J2.34(UART_CTS) ; also on sheet 36
SOC_UART1_RTS_BT: J2.36(UART_RTS) ; also on sheet 36
SOC_UART1_RX_BT: J2.22(UART_RXD) ; also on sheet 36
SOC_UART1_TX_BT: R254.2 ; also on sheet 36
SoC_WLAN_SDIO_RST: U1.13(B1) ; also on sheet 39
USB_DM: J2.5(USB_D-) TP97.1(TP)
USB_DP: J2.3(USB_D+) TP98.1(TP)
WL_LT_EN: R6.1 R7.2 U1.8(OE) ; also on sheet 39
WLAN_ALERT_1V8: R8.2 U1.5(A4)
WLAN_ALERTn: R2.1 U1.10(B4) ; also on sheet 39
WLAN_EN: R11.1 R12.2 U1.4(A3) U18.F22(MMC2_SDCD)
WLAN_EN_3V3: R10.2 U1.11(B3)
WLAN_IRQ: J2.21(SDIO_WAKE#) R262.1 U18.E21(MMC2_SDWP)
WLAN_SDIO_RST: J2.23(SDIO_RESET#/TX_BLANKING) R9.1 U1.2(A1)
N15951749: C177.1 R264.2 R272.2 U56.1(TRI-STATE) U56.4(VDD)
N15952254: R280.1 U56.3(OUTPUT)
N16878497: R368.1 TP100.1(TP) U28.H5(DS)
N16880083: R106.2 R353.1 U24.1(A)
N18121816: J21.2 R261.1
N18121892: J21.4 R260.1
N18121904: J21.6 R259.1
N18121916: J21.9 R244.2
N18121928: J21.12 R258.1
N18121940: J21.14 R257.1
N22734804: J2.32(UART_TXD) R254.1
N22816067: J2.62(ALERT#) R8.1

Not connected (* = marked no-connect by the designer): J2 35(PETP0)* 37(PETN0)* 38(VENDOR_DEFINED1)* 40(VENDOR_DEFINED2)* 41(PERP0)* 42(VENDOR_DEFINED3)* 43(PERN0)* 44(COEX3)* 46(COEX_RXD)* 47(REFCLKP0)* 48(COEX_TXD)* 49(REFCLKN0)* 52(PERST0#)* 53(CLKREQ0#)* 55(PEWAKE0#)* 58(I2C_DATA)* 59(RESERVED/PETP1)* 60(I2C_CLK)* 61(RESERVED/PETN1)* 64(RESERVED)* 65(RESERVED/PERP1)* 66(UIM_SWP/PERST1#)* 67(RESERVED/PERN1)* 68(UIM_POWER_SNK/CLKREQ1#)* 70(UIM_POWER_SRC/GPIO1/PEWAKE#)* 71(RESERVED/REFCLKP1)* 73(RESERVED/REFCLKN1)* SH3*; U1 6(NC1)* 9(NC2)*; U20 4(CT)*; U22 4(NC1)* 9(NC2)*; U28 A1(NC1)* A2(NC2)* A7(RFU1)* A8(NC3)* A9(NC4)* A10(NC5)* A11(NC6)* A12(NC7)* A13(NC8)* A14(NC9)* B1(NC10)* B7(NC11)* B8(NC12)* B9(NC13)* B10(NC14)* B11(NC15)* B12(NC16)* B13(NC17)* B14(NC18)* C1(NC19)* C3(NC20)* C5(NC21)* C7(NC22)* C8(NC23)* C9(NC24)* C10(NC25)* C11(NC26)* C12(NC27)* C13(NC28)* C14(NC29)* D1(NC30)* D2(NC31)* D3(NC32)* D4(NC33)* D12(NC34)* D13(NC35)* D14(NC36)* E1(NC37)* E2(NC38)* E3(NC39)* E5(RFU2)* E8(VSF1)* E9(VSF2)* E10(VSF3)* E12(NC40)* E13(NC41)* E14(NC42)* F1(NC43)* F2(NC44)* F3(NC45)* F10(VSF4)* F12(NC46)* F13(NC47)* F14(NC48)* G1(NC49)* G2(NC50)* G3(NC51)* G10(VSF5)* G12(NC52)* G13(NC53)* G14(NC54)* H1(NC55)* H2(NC56)* H3(NC57)* H12(NC58)* H13(NC59)* H14(NC60)* J1(NC61)* J2(NC62)* J3(NC63)* J12(NC64)* J13(NC65)* J14(NC66)* K1(NC67)* K2(NC68)* K3(NC69)* K6(RFU3)* K7(RFU4)* K10(VSF6)* K12(NC70)* K13(NC71)* K14(NC72)* L1(NC73)* L2(NC74)* L3(NC75)* L12(NC76)* L13(NC77)* L14(NC78)* M1(NC79)* M2(NC80)* M3(NC81)* M7(NC82)* M8(NC83)* M9(NC84)* M10(NC85)* M11(NC86)* M12(NC87)* M13(NC88)* M14(NC89)* N1(NC90)* N3(NC91)* N6(NC92)* N7(NC93)* N8(NC94)* N9(NC95)* N10(NC96)* N11(NC97)* N12(NC98)* N13(NC99)* N14(NC100)* P1(NC101)* P2(NC102)* P7(NC103)* P8(NC104)* P9(NC105)* P10(VSF7)* P11(NC106)* P12(NC107)* P13(NC108)* P14(NC109)*; U79 2(NC)* 3(IO1)*

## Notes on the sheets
sheet 17
- M.2 INTERFACE - SDIO
- As per the connector specification
  Each Pin supports 1 Amp of current
- SoC_MAIN_UART1_RXD
- SoC_MAIN_UART1_TXD
- SoC_MAIN_UART1_CTS
- SoC_MAIN_UART1_RTS
- M.2 LEVEL TRANSLATOR
- D-Note :-
  Add a bulk cap
  when oscillator
  is used
- CAD Note :-
  Place Series resistors for MMC2
  signals as TRI-PAD to avoid stub
- D-Note :-
  Ok to use 10K, 5%
- Design Note: WL_LT_EN = Active High
- Cad Note :-
  Place R1 & R2 close to each other to avoid stub.
sheet 18
- D-Note :-
  This family of processor implements a soft PHY
  for eMMC interface. The pulls required for D0,
  Clock and other eMMC interface control signals
  are recommended to be implemented externally.
- SOC - MMC Interface
- D-Note :-
  0E provision on MMC0_CLK
  helps improve signal integrity
- eMMC FLASH
- D-Note :-
  MMC0 interface is compliant with the
  JEDEC eMMC electrical standard v5.1
  (JESD84-B51)
- D-Note :-
  Add additional decaps as required
  Refer SK-AM62P-LP schematics
- D-Note :-
  For D7..D1 eMMC device is expected to have the
  pullups enabled by default. The eMMC host/phy
  disables the eMMC device pullups and enables SOC
  internal pullups. Provision for external pullups is
  optional or the pullups can be deleted
- CAD Note :-
  Place SOC clock output
  pulldown resistor near to
  the clock input pin of the
  attached (memory) device
- D-Note :-
  Ok to use standard
  47K or similar
  resistor for all
  the parallel pulls
- R-Note :-
  What is the reason we selected
  pulldown instead of pullup for EMMC,
  SD card or other peripherals?
  Because there are cases where the
  clock is stopped or paused in a low
  logic state and the pull-down option
  is consistent with this logic state.
- D-Note :-
  Ensure eMMC_RSTn Reset input is enabled
  in the eMMC device (eMMC non-volatile
  configuration space) for the reset
  logic to be functional
- D-Note :-
  The GPIO reset option makes it possible
  for software to reset the attached
  device (eMMC or OSPI or SD card or OLDI0
  or EPHY) without resetting the entire
  processor if there is a case where the
  peripheral becomes unresponsive.
- eMMC FLASH RESET
- D-Note :-
  You could eliminate the GPIO option and only use the
  reset output ( Warm or cold), where software forces a
  warm reset if the peripheral becomes unresponsive.
  However, this will reset the entire device rather than
  trying to recover the specific peripheral without
  resetting the entire device.
- D-Note :-
  Ok to use
  standard 47K
  or similar
  resistor
- D-Note :-
  Add a series resistor to the SOC GPIO
  input for isolation or testing. Refer
  SK-AM62P-LP schematics
- Design Note: eMMC_RSTn Active low
  s/w control
- D-Note :-
  In case ANDing logic is not used and the processor
  Main Domain warm reset status output (RESETSTATz)
  is used to reset the attached device, ensure the
  IO voltage level of the attached device matches
  the RESETSTATz IO voltage  level. A level
  translator is recommended to match the IO voltage
  level. A resistor divider could be used
  alternatively, provided optimum impedance value of
  the  resistor divider is selected. If too high the
  rise/fall  time of the eMMC reset input could be
  slow and introduce  too much delay. If too low it
  will cause the AM62x to source too much
  steady-state current during normal  operation.
- D-Note :-
  ANDing logic additionally performs level translation
  Verify the Reset IO level compatibility before
  optimizing the reset ANDing logic.IO level mismatch
  could cause supply leakage and affect SOC operation
sheet 19
- SD CARD INTERFACE
- D-Note :-
  This power switch, along with the reset logic, and the host IO power supply circuit is
  required to support UHS-I SD Cards which begins communications using 3.3V signal levels
  and later change to 1.8V signal levels when changing to one of the faster data transfer
  speeds. Cycling power to the SD Card is the only way to put it back into 3.3V mode since
  SD Cards do not have a reset pin. The host IO power supply must power off/on and change
  voltage at the same time as the SD Card. These circuits and the software driver operating
  the signals sourcing these circuits ensure both devices are off, or on and operating at
  the same IO voltage at the same time.
- LOAD SWITCH
- SD CARD LOAD SWITCH
           RESET LOGIC
- D-Note :-
  ANDing logic could be
  optimized to 2 input AND gate
  Use RESETSTATz and the SOC IO
  as inputs
- D-Note :-
  CT - Add a 220 pF or higher cap for
  SD card supply slew rate control
- D-Note :-
  For UHS-I  operation, the
  pullups are recommended to
  be connected to the
  3.3V/1.8V switched LDO
  output
- R-Note :-
  MMC1_CLK pullup is a DNI
- D-Note :-
  Ensure internal pullups are not configured when 10K
  external pullups are used. As a good design practice, a
  47K pullup is recommended to ensure the pullup value is
  within the SD card specification, when internal pulls
  are enabled unexpectedly. This way the resulting pull
  resistance will still be within the specified.
- D-Note :-
  Add a filter cap
- CAD Note :-
  Place near SD Card Connector
